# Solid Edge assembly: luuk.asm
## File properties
Author: Mac
Template: Normal.asm
Last saved by: Mac
Revision: 4
Application: Solid Edge
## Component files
luuk.par
luugi_lukk.par
hing.asm
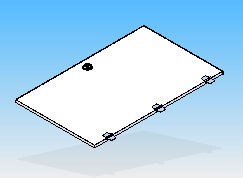
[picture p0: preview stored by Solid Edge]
